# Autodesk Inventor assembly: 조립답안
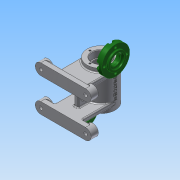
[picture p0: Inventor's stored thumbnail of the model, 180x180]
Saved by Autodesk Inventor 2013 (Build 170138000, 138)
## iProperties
Created: 2015-11
Part Number: 조립답안
Document SubType Name: Assembly
Designer: Administrator
Author: Administrator
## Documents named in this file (3)
- C:\Users\Administrator\Desktop\451110V1043\조립답안.iam
- C:\Users\Administrator\Desktop\451110V1043\본체.ipt
- C:\Users\Administrator\Desktop\451110V1043\커버.ipt
